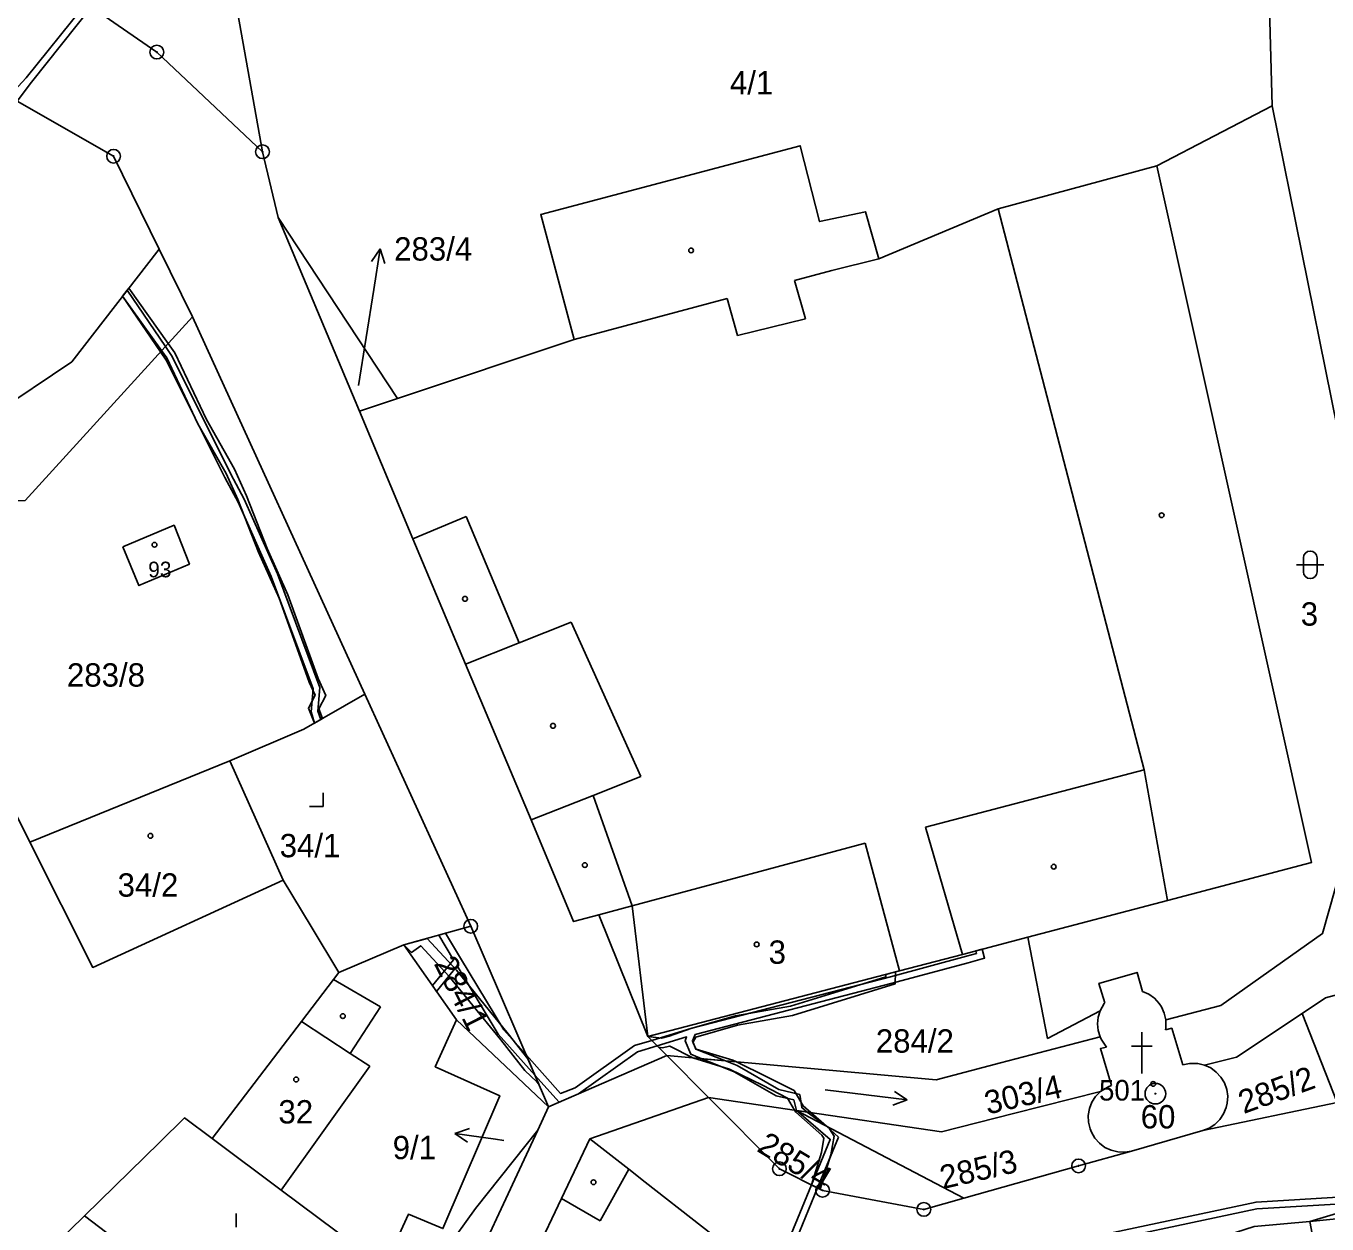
# Model space of a CAD drawing. Extents: x -779723 to -777378, y -1011169 to -1009297.
# Drawn here: x -779222.9 to -779128.1, y -1010301.7 to -1010214.5 of the extents above; entities that cross this region are included whole.
import ezdxf

# ---------------------------------------------------------------- set-up
doc = ezdxf.new("R2010")
doc.units = 0
for name, color, linetype in [('Hranice parcel', 7, 'Continuous'), ('Parcelní čísla', 7, 'Continuous'), ('Pop  PČ popisy', 7, 'Continuous'), ('Vnitřní kresba', 7, 'Continuous'), ('Věcná břemena k části', 7, 'Continuous'), ('Značky bodu BP', 7, 'Continuous'), ('Značky budov', 7, 'Continuous'), ('Značky kultur', 7, 'Continuous')]:
    doc.layers.add(name, color=color, linetype=linetype)

msp = doc.modelspace()

# ---------------------------------------------------------------- linework, layer by layer
at = {"layer": 'Hranice parcel'}
for p, q in [((-779132.14, -1010220.3), (-779132.76, -1010196.68)), ((-779207.96, -1010210.85), (-779205.69, -1010223.63)), ((-779132.14, -1010220.3), (-779140.53, -1010224.66)), ((-779205.69, -1010223.63), (-779204.56, -1010228.41)), ((-779204.56, -1010228.41), (-779198.63, -1010242.53)), ((-779204.56, -1010228.41), (-779195.85, -1010241.6)), ((-779210.79, -1010235.65), (-779213.22, -1010230.72)), ((-779198.24, -1010263.13), (-779210.79, -1010235.65)), ((-779195.85, -1010241.6), (-779198.63, -1010242.53)), ((-779190.52, -1010280.05), (-779198.24, -1010263.13)), ((-779208.06, -1010267.99), (-779222.63, -1010273.91)), ((-779208.06, -1010267.99), (-779204.18, -1010276.69)), ((-779222.63, -1010273.91), (-779224.53, -1010270.12)), ((-779195.39, -1010281.41), (-779190.52, -1010280.05)), ((-779184.85, -1010293.19), (-779190.52, -1010280.05)), ((-779195.39, -1010281.41), (-779200.12, -1010283.41)), ((-779191.55, -1010286.87), (-779195.39, -1010281.41)), ((-779191.55, -1010286.87), (-779184.85, -1010293.19)), ((-779129.95, -1010286.4), (-779127.4, -1010292.89)), ((-779177.62, -1010288.07), (-779176.23, -1010289.47)), ((-779176.23, -1010289.47), (-779184.85, -1010293.19)), ((-779173.19, -1010292.52), (-779176.23, -1010289.47)), ((-779181.85, -1010295.53), (-779173.19, -1010292.52)), ((-779166.79, -1010293.46), (-779173.19, -1010292.52)), ((-779184.85, -1010293.19), (-779185.64, -1010294.9)), ((-779166.79, -1010293.46), (-779154.6, -1010299.85)), ((-779127.4, -1010292.89), (-779137.19, -1010294.93)), ((-779142.38, -1010296.42), (-779137.19, -1010294.93)), ((-779129.38, -1010301.54), (-779107.13, -1010294.85))]:
    msp.add_line(p, q, dxfattribs=at)
for points in [[(-779242.79, -1010195.65), (-779223.48, -1010209.38), (-779213.39, -1010216.37), (-779205.69, -1010223.63)], [(-779213.22, -1010230.72), (-779219.59, -1010238.93), (-779225.31, -1010242.76), (-779234.3, -1010244.39), (-779244.61, -1010237.88), (-779244.88, -1010233.78), (-779245.13, -1010229.97), (-779245.92, -1010218.02)], [(-779223.57, -1010219.94), (-779216.54, -1010223.96), (-779213.22, -1010230.72)], [(-779139.88, -1010286.86), (-779135.87, -1010285.81), (-779128.47, -1010280.58), (-779123.49, -1010263.01), (-779132.14, -1010220.3)], [(-779140.53, -1010224.66), (-779152.1, -1010227.79), (-779160.79, -1010231.43), (-779161.77, -1010228), (-779165.11, -1010228.72), (-779166.52, -1010223.19), (-779185.42, -1010228.21), (-779182.98, -1010237.3), (-779195.85, -1010241.6)], [(-779149.94, -1010280.84), (-779139.76, -1010278.16), (-779129.26, -1010275.39), (-779140.53, -1010224.66)], [(-779234.91, -1010249.39), (-779222.98, -1010249.03), (-779210.79, -1010235.65)], [(-779198.63, -1010242.53), (-779194.73, -1010251.82), (-779190.9, -1010260.95), (-779186.13, -1010272.3), (-779183.03, -1010279.71), (-779181.19, -1010279.22), (-779177.62, -1010288.07)], [(-779215.86, -1010252.41), (-779214.7, -1010255.23), (-779211.01, -1010253.67), (-779212.13, -1010250.84), (-779215.86, -1010252.41)], [(-779198.24, -1010263.13), (-779202.67, -1010265.7), (-779208.06, -1010267.99)], [(-779222.63, -1010273.91), (-779218.06, -1010283.04), (-779204.18, -1010276.69)], [(-779204.18, -1010276.69), (-779202.14, -1010280.06), (-779200.12, -1010283.41)], [(-779177.62, -1010288.07), (-779159.28, -1010283.29), (-779154.7, -1010282.1), (-779149.94, -1010280.84)], [(-779149.94, -1010280.84), (-779148.5, -1010288.21), (-779144.67, -1010286.2)], [(-779200.12, -1010283.41), (-779200.51, -1010283.92), (-779202.85, -1010286.98), (-779209.36, -1010295.51)], [(-779141.57, -1010284.79), (-779141.98, -1010283.41), (-779144.76, -1010284.21), (-779144.33, -1010285.63)], [(-779139.88, -1010286.86), (-779139.992, -1010286.371), (-779140.199, -1010285.913), (-779140.366, -1010285.661), (-779140.706, -1010285.292), (-779141.113, -1010284.998), (-779141.57, -1010284.79)], [(-779125.19, -1010284.44), (-779128.24, -1010285.26), (-779129.95, -1010286.4)], [(-779144.33, -1010285.63), (-779144.37, -1010285.68), (-779144.67, -1010286.2)], [(-779196.83, -1010304.88), (-779195.06, -1010301.02), (-779192.55, -1010302.07), (-779188.41, -1010292.39), (-779193.1, -1010290.28), (-779191.55, -1010286.87)], [(-779144.67, -1010286.2), (-779144.816, -1010286.673), (-779144.864, -1010287.144), (-779144.816, -1010287.637), (-779144.67, -1010288.11)], [(-779139.9, -1010287.6), (-779139.88, -1010287.47), (-779139.88, -1010286.86)], [(-779129.95, -1010286.4), (-779134.73, -1010289.57), (-779137.06, -1010290.16)], [(-779138.64, -1010290.15), (-779139.45, -1010287.47), (-779139.9, -1010287.6)], [(-779176.23, -1010289.47), (-779156.62, -1010291.23), (-779151.93, -1010290), (-779144.67, -1010288.11)], [(-779144.67, -1010288.11), (-779144.6, -1010288.27), (-779144.21, -1010288.84)], [(-779144.21, -1010288.84), (-779144.64, -1010288.96), (-779143.83, -1010291.64)], [(-779137.06, -1010290.16), (-779137.554, -1010290.049), (-779137.639, -1010290.04), (-779138.145, -1010290.045), (-779138.64, -1010290.15)], [(-779137.19, -1010294.93), (-779136.725, -1010294.747), (-779136.305, -1010294.475), (-779135.949, -1010294.125), (-779135.669, -1010293.711), (-779135.477, -1010293.249), (-779135.402, -1010292.926), (-779135.371, -1010292.427), (-779135.441, -1010291.932), (-779135.607, -1010291.461), (-779135.864, -1010291.032), (-779136.202, -1010290.663), (-779136.606, -1010290.369), (-779137.06, -1010290.16)], [(-779143.83, -1010291.64), (-779144.03, -1010291.71), (-779144.65, -1010292.08)], [(-779154.6, -1010299.85), (-779157.51, -1010300.67), (-779164.89, -1010299.28), (-779168.03, -1010297.71), (-779173.19, -1010292.52)], [(-779144.65, -1010292.08), (-779150.97, -1010293.68), (-779156.22, -1010295.01), (-779166.79, -1010293.46)], [(-779144.65, -1010292.08), (-779144.998, -1010292.44), (-779145.268, -1010292.862), (-779145.449, -1010293.33), (-779145.533, -1010293.823), (-779145.517, -1010294.324), (-779145.402, -1010294.812), (-779145.307, -1010295.049), (-779145.053, -1010295.48), (-779144.718, -1010295.853), (-779144.315, -1010296.151), (-779143.862, -1010296.364), (-779143.375, -1010296.482), (-779142.874, -1010296.501), (-779142.38, -1010296.42)], [(-779209.36, -1010295.51), (-779211.37, -1010294.01), (-779213.17, -1010295.76), (-779218.66, -1010301.14)], [(-779209.36, -1010295.51), (-779204.33, -1010299.27), (-779198.99, -1010303.26)], [(-779194.49, -1010306.63), (-779190.18, -1010300.61), (-779185.64, -1010294.9)], [(-779185.64, -1010294.9), (-779191.98, -1010308.5), (-779194.49, -1010306.63)], [(-779181.85, -1010295.53), (-779183.92, -1010299.88), (-779187.65, -1010307.74)], [(-779169.61, -1010305.1), (-779177.81, -1010298.69), (-779179.01, -1010297.75), (-779181.85, -1010295.53)], [(-779142.38, -1010296.42), (-779146.24, -1010297.5), (-779154.6, -1010299.85)], [(-779113.91, -1010300.03), (-779116.55, -1010300.26), (-779129.38, -1010301.54)], [(-779241.34, -1010326.4), (-779229.64, -1010317.38), (-779225.92, -1010308.91), (-779220.82, -1010303.25), (-779218.66, -1010301.14)], [(-779218.66, -1010301.14), (-779215.5, -1010303.55), (-779204.57, -1010311.9), (-779199.75, -1010305.93), (-779198.99, -1010303.26)], [(-779129.38, -1010301.54), (-779133.45, -1010301.92), (-779148.16, -1010306.65)], [(-779112.91, -1010324.76), (-779116.23, -1010317.61), (-779121.94, -1010319.13), (-779123.32, -1010317.03), (-779123.62, -1010314.23), (-779124.34, -1010308.48), (-779126.89, -1010308.67), (-779128.03, -1010308.75), (-779129.38, -1010301.54)]]:
    msp.add_lwpolyline(points, dxfattribs=at)
at = {"layer": 'Pop  PČ popisy'}
for p, q in [((-779197.111, -1010230.706), (-779197.762, -1010231.617)), ((-779197.58, -1010233.67), (-779197.111, -1010230.706)), ((-779197.111, -1010230.706), (-779196.773, -1010231.773)), ((-779198.7, -1010240.65), (-779197.58, -1010233.67)), ((-779191.682, -1010295.142), (-779190.62, -1010294.786)), ((-779188.71, -1010295.56), (-779191.682, -1010295.142)), ((-779191.682, -1010295.142), (-779190.76, -1010295.778)), ((-779188.12, -1010295.64), (-779188.71, -1010295.56))]:
    msp.add_line(p, q, dxfattribs=at)
at = {"layer": 'Vnitřní kresba'}
for p, q in [((-779152.1, -1010227.79), (-779141.46, -1010268.66)), ((-779164.21, -1010232.28), (-779160.79, -1010231.43)), ((-779166.93, -1010233.01), (-779164.21, -1010232.28)), ((-779166.93, -1010233.01), (-779166.12, -1010235.81)), ((-779182.98, -1010237.3), (-779171.83, -1010234.32)), ((-779171.83, -1010234.32), (-779171.09, -1010237.01)), ((-779171.09, -1010237.01), (-779166.12, -1010235.81)), ((-779194.73, -1010251.82), (-779190.86, -1010250.19)), ((-779186.99, -1010259.4), (-779190.86, -1010250.19)), ((-779186.99, -1010259.4), (-779183.21, -1010257.9)), ((-779178.12, -1010269.14), (-779183.21, -1010257.9)), ((-779190.9, -1010260.95), (-779186.99, -1010259.4)), ((-779141.46, -1010268.66), (-779157.38, -1010272.82)), ((-779141.46, -1010268.66), (-779139.76, -1010278.16)), ((-779181.59, -1010270.51), (-779178.12, -1010269.14)), ((-779186.13, -1010272.3), (-779181.59, -1010270.51)), ((-779178.75, -1010278.56), (-779181.59, -1010270.51)), ((-779157.38, -1010272.82), (-779154.7, -1010282.1)), ((-779178.75, -1010278.56), (-779161.78, -1010273.99)), ((-779161.78, -1010273.99), (-779159.28, -1010283.29)), ((-779181.19, -1010279.22), (-779178.75, -1010278.56)), ((-779177.62, -1010288.07), (-779178.75, -1010278.56)), ((-779197.09, -1010285.92), (-779200.51, -1010283.92)), ((-779199.3, -1010289.31), (-779197.09, -1010285.92)), ((-779202.85, -1010286.98), (-779199.3, -1010289.31)), ((-779199.3, -1010289.31), (-779197.88, -1010290.24)), ((-779204.33, -1010299.27), (-779197.88, -1010290.24)), ((-779179.01, -1010297.75), (-779181.08, -1010301.49)), ((-779183.92, -1010299.88), (-779181.08, -1010301.49))]:
    msp.add_line(p, q, dxfattribs=at)
at = {"layer": 'Věcná břemena k části'}
for points in [[(-779218.14, -1010213.08), (-779218.5, -1010212.83), (-779219.41, -1010212.2), (-779219.92, -1010211.85), (-779220.81, -1010211.23), (-779218.81, -1010213.14), (-779222.9, -1010218.24), (-779224.1, -1010219.53), (-779223.57, -1010219.94), (-779222.52, -1010218.56)], [(-779201.59, -1010264.21), (-779201.08, -1010263.24), (-779201.64, -1010262), (-779203.84, -1010255.9), (-779205.34, -1010252.52), (-779206.85, -1010248.69), (-779207.73, -1010246.75), (-779209.78, -1010243.14), (-779212.07, -1010238.28), (-779212.56, -1010237.59), (-779215.44, -1010233.58), (-779215.88, -1010234.15), (-779213.04, -1010238.12), (-779212.67, -1010238.64), (-779210.4, -1010243.46), (-779208.35, -1010247.07), (-779207.49, -1010248.97), (-779205.98, -1010252.8), (-779204.48, -1010256.16), (-779202.28, -1010262.26), (-779201.86, -1010263.22), (-779202.35, -1010264.17), (-779201.91, -1010265.26), (-779201.31, -1010264.91)], [(-779201.44, -1010264.99), (-779201.65, -1010264.37), (-779201.51, -1010262.66), (-779204.61, -1010254.38), (-779207.02, -1010248.93), (-779207.99, -1010247.11), (-779212.28, -1010238.55), (-779212.77, -1010237.82), (-779215.55, -1010233.72), (-779215.88, -1010234.15), (-779213.12, -1010238.21), (-779212.72, -1010238.81), (-779208.43, -1010247.35), (-779207.46, -1010249.15), (-779205.07, -1010254.56), (-779202.01, -1010262.74), (-779202.15, -1010264.43), (-779201.91, -1010265.26)], [(-779185.71, -1010291.37), (-779185.56, -1010291.54), (-779186.35, -1010289.7), (-779187.79, -1010287.87), (-779191.56, -1010283.25), (-779193.69, -1010280.94), (-779195.39, -1010281.41), (-779194.83, -1010281.95), (-779194.16, -1010281.46), (-779192.08, -1010283.71), (-779188.33, -1010288.31), (-779186.58, -1010290.56)], [(-779185.84, -1010290.88), (-779186.47, -1010289.44), (-779188.12, -1010287.6), (-779191.27, -1010282.37), (-779192.36, -1010280.56), (-779192.85, -1010280.7), (-779191.78, -1010282.48), (-779193.31, -1010284.37), (-779193.01, -1010284.79), (-779191.51, -1010282.93), (-779188.52, -1010287.9)], [(-779171.95, -1010289.85), (-779174.11, -1010288.99), (-779174.37, -1010288.39), (-779174.16, -1010287.92), (-779159.82, -1010284.2), (-779154.27, -1010282.7), (-779153.08, -1010282.36), (-779153.25, -1010281.72), (-779153.73, -1010281.84), (-779153.68, -1010282.02), (-779154.41, -1010282.22), (-779159.95, -1010283.72), (-779174.41, -1010287.47), (-779177.33, -1010288.36), (-779176.93, -1010288.76), (-779174.79, -1010288.11), (-779174.91, -1010288.39), (-779174.49, -1010289.37), (-779173.68, -1010289.7)], [(-779176.58, -1010288.89), (-779176.02, -1010288.77), (-779174.34, -1010289.64), (-779171.17, -1010289.92), (-779171.42, -1010289.8), (-779174.09, -1010288.99), (-779174.33, -1010288.52), (-779174.13, -1010288.12), (-779171.08, -1010287.24), (-779167.07, -1010286.55), (-779159.61, -1010284.25), (-779159.58, -1010283.37), (-779160.28, -1010283.55), (-779160.29, -1010283.73), (-779167.23, -1010285.87), (-779171.24, -1010286.56), (-779174.48, -1010287.5), (-779176.07, -1010288.06), (-779176.62, -1010288.19), (-779177.62, -1010288.07), (-779176.84, -1010288.86)], [(-779176.93, -1010288.76), (-779177.33, -1010288.36), (-779178.59, -1010288.74), (-779182.91, -1010291.81), (-779183.97, -1010292.22), (-779186.47, -1010289.44), (-779185.84, -1010290.88), (-779184.09, -1010292.86), (-779182.67, -1010292.25), (-779178.37, -1010289.2)], [(-779174.34, -1010289.64), (-779171.68, -1010290.46), (-779169.27, -1010291.63), (-779167.45, -1010292.56), (-779166.93, -1010293.44), (-779165.74, -1010293.61), (-779166.3, -1010293.13), (-779166.95, -1010292.02), (-779168.95, -1010291.01), (-779171.17, -1010289.92)], [(-779166, -1010293.58), (-779166.4, -1010293.25), (-779166.55, -1010292.3), (-779168.08, -1010291.93), (-779171.11, -1010290.19), (-779171.95, -1010289.85), (-779173.68, -1010289.7), (-779171.33, -1010290.65), (-779168.26, -1010292.39), (-779166.99, -1010292.7), (-779166.79, -1010293.46)], [(-779164.28, -1010296.69), (-779164.05, -1010295.33), (-779164.39, -1010294.79), (-779164.6, -1010294.61), (-779165.74, -1010293.61), (-779166.93, -1010293.44), (-779166.84, -1010293.59), (-779164.93, -1010295.25), (-779164.79, -1010295.47), (-779164.96, -1010296.53), (-779165.69, -1010298.88), (-779165.07, -1010299.19)], [(-779163.73, -1010295.41), (-779164.6, -1010294.61), (-779166, -1010293.58), (-779166.79, -1010293.46), (-779164.33, -1010295.57), (-779165.69, -1010298.88), (-779165.25, -1010299.1)], [(-779165.25, -1010299.1), (-779165.69, -1010298.88), (-779168.03, -1010304.53), (-779169.81, -1010304.95), (-779169.61, -1010305.1), (-779168.76, -1010305.45), (-779168.92, -1010305.23), (-779167.67, -1010304.97)], [(-779124.64, -1010300.11), (-779122.56, -1010299.49), (-779133.3, -1010300.13), (-779147.73, -1010303.19), (-779149.42, -1010303.43), (-779152.32, -1010304.88), (-779155.18, -1010307.73), (-779154.33, -1010307.6), (-779152.02, -1010305.3), (-779149.26, -1010303.91), (-779147.64, -1010303.68), (-779133.24, -1010300.63)]]:
    msp.add_lwpolyline(points, close=True, dxfattribs=at)
at = {"layer": 'Značky bodu BP'}
for centre, radius in [((-779213.39, -1010216.37), 0.5), ((-779213.39, -1010216.37), 0.0303), ((-779216.54, -1010223.96), 0.5), ((-779205.69, -1010223.63), 0.5), ((-779205.69, -1010223.63), 0.0303), ((-779216.54, -1010223.96), 0.0303), ((-779190.52, -1010280.05), 0.5), ((-779190.52, -1010280.05), 0.0303), ((-779140.64, -1010292.24), 0.75), ((-779140.64, -1010292.24), 0.03), ((-779168.03, -1010297.71), 0.5), ((-779146.24, -1010297.5), 0.5), ((-779146.24, -1010297.5), 0.0303), ((-779168.03, -1010297.71), 0.0303), ((-779164.89, -1010299.28), 0.5), ((-779164.89, -1010299.28), 0.0303), ((-779157.51, -1010300.67), 0.5), ((-779157.51, -1010300.67), 0.0303)]:
    msp.add_circle(centre, radius, dxfattribs=at)
at = {"layer": 'Značky budov'}
for p, q in [((-779141.62, -1010287.77), (-779141.62, -1010290.77)), ((-779142.371, -1010288.771), (-779140.869, -1010288.771))]:
    msp.add_line(p, q, dxfattribs=at)
for centre in [(-779174.467, -1010230.819), (-779140.187, -1010250.109), (-779213.557, -1010252.259), (-779190.937, -1010256.199), (-779184.527, -1010265.449), (-779213.857, -1010273.459), (-779182.207, -1010275.589), (-779148.047, -1010275.709), (-779169.687, -1010281.369), (-779199.837, -1010286.589), (-779203.237, -1010291.209), (-779140.797, -1010291.529), (-779181.577, -1010298.689)]:
    msp.add_circle(centre, 0.175, dxfattribs=at)
at = {"layer": 'Značky kultur'}
for p, q in [((-779130.361, -1010253.721), (-779128.359, -1010253.721)), ((-779129.861, -1010253.221), (-779129.861, -1010254.222)), ((-779128.859, -1010254.222), (-779128.859, -1010253.221)), ((-779201.27, -1010271.33), (-779201.27, -1010270.33)), ((-779202.271, -1010271.33), (-779201.27, -1010271.33)), ((-779164.692, -1010291.965), (-779158.736, -1010292.696)), ((-779158.736, -1010292.696), (-779159.767, -1010293.075)), ((-779158.736, -1010292.696), (-779159.645, -1010292.079)), ((-779207.6, -1010301.97), (-779207.6, -1010300.97))]:
    msp.add_line(p, q, dxfattribs=at)
for centre, start, end in [((-779129.36, -1010253.221), 0, 180), ((-779129.36, -1010254.221), 180, 359.98789)]:
    msp.add_arc(centre, 0.5, start, end, dxfattribs=at)

# ---------------------------------------------------------------- texts
at = {"layer": 'Parcelní čísla'}
for s, height, p in [('4/1', 1.7, (-779171.64, -1010219.46)), ('283/4', 1.7, (-779196.1, -1010231.559)), ('93', 1.14, (-779214.02, -1010254.63)), ('3', 1.7, (-779130.05, -1010258.15)), ('283/8', 1.7, (-779219.94, -1010262.59)), ('34/1', 1.7, (-779204.44, -1010275.02)), ('34/2', 1.7, (-779216.25, -1010277.89)), ('3', 1.7, (-779168.82, -1010282.78)), ('284/2', 1.7, (-779161.01, -1010289.25)), ('32', 1.7, (-779204.53, -1010294.41)), ('60', 1.7, (-779141.71, -1010294.77)), ('9/1', 1.7, (-779196.208, -1010297.01))]:
    msp.add_text(s, height=height, dxfattribs=at).set_placement(p)
for s, rotation, p in [('284/1', 297, (-779193.237, -1010282.755)), ('303/4', 13, (-779152.868, -1010293.768)), ('285/2', 20, (-779134.209, -1010293.728)), ('285/4', 329, (-779169.757, -1010296.388)), ('285/3', 13, (-779156.118, -1010299.198))]:
    msp.add_text(s, height=1.7, rotation=rotation, dxfattribs=at).set_placement(p)
at = {"layer": 'Značky bodu BP'}
msp.add_text('501', height=1.5, dxfattribs=at).set_placement((-779144.743, -1010292.74))

doc.saveas('drawing.dxf')
